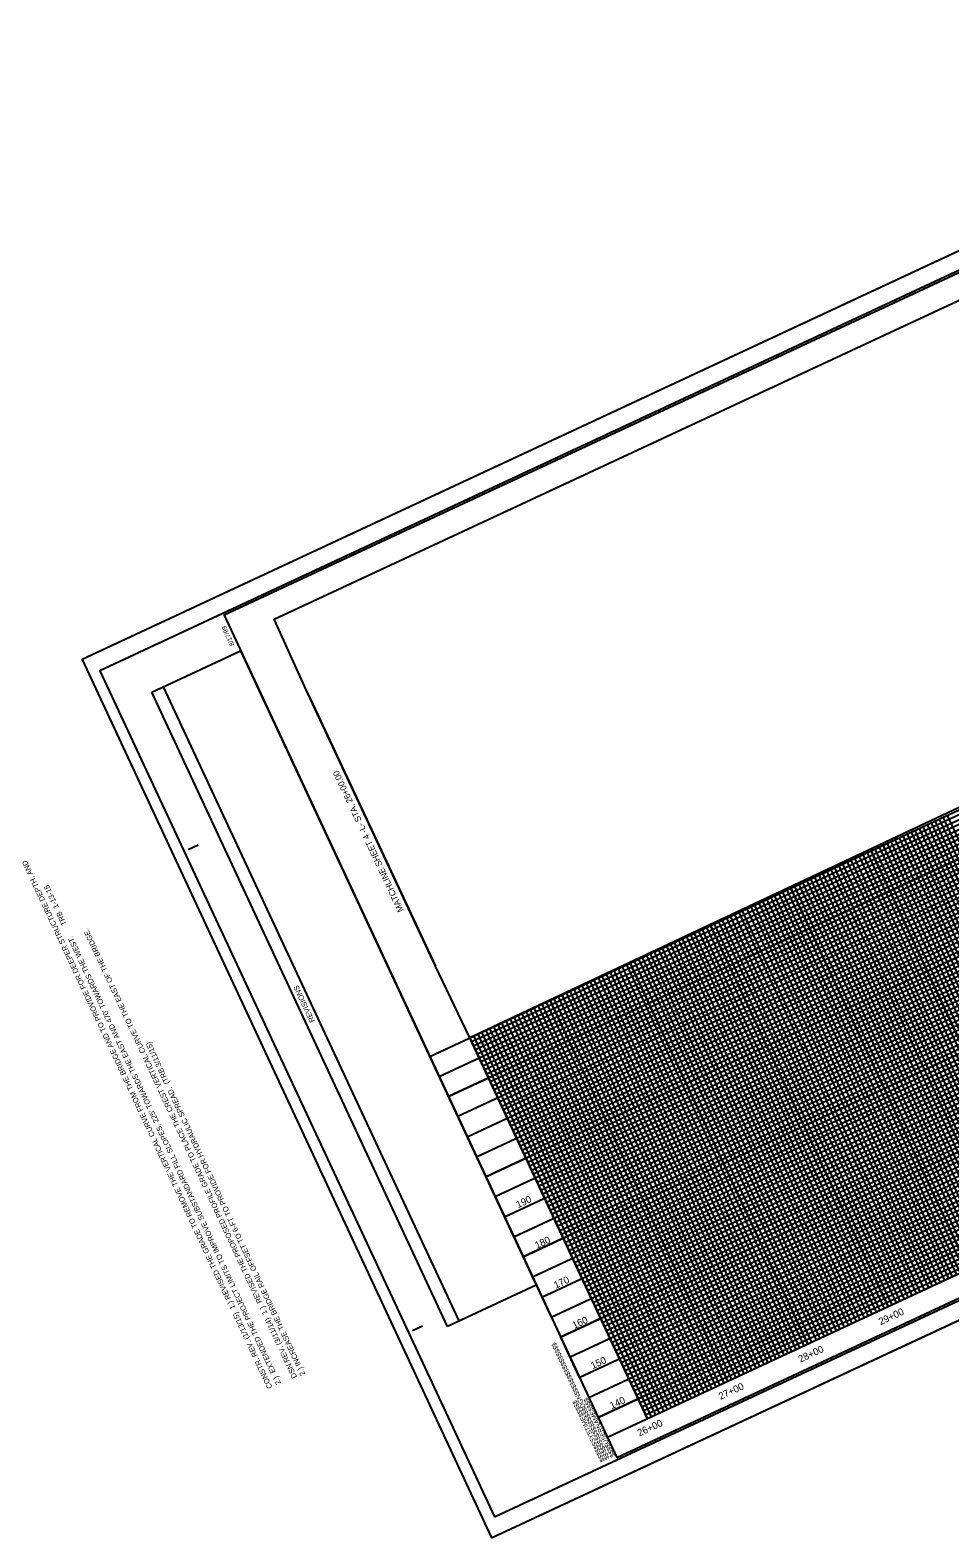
# Model space of a CAD drawing. Extents: x 2321825 to 2323872, y 921700 to 923436.
# Drawn here: x 2321825 to 2322864, y 921700 to 923403 of the extents above; entities that cross this region are included whole.
import ezdxf

# ---------------------------------------------------------------- set-up
doc = ezdxf.new("R2010")
doc.units = 0
for name, color, linetype in [('Default', 7, 'Continuous'), ('Matchline', 7, 'Continuous'), ('Matchline Text', 7, 'Continuous'), ('Sheet Block Revision CELL', 7, 'Continuous'), ('Sheet Block System Information CELL', 7, 'Continuous'), ('Sheet Cutting Line CELL', 7, 'Continuous'), ('Sheet DOT Grid CELL', 7, 'Continuous'), ('Sheet Layout Plan Border', 7, 'Continuous'), ('Sheet Layout Profile Border Port 2', 7, 'Continuous'), ('Sheet Plan And Profile CELL', 7, 'Continuous'), ('Sheet Plot Border Inside CELL', 7, 'Continuous'), ('Sheet Plot Border Outside CELL', 7, 'Continuous'), ('Sheet Profile Grid Major CELL', 7, 'Continuous'), ('Sheet Profile Grid Middle CELL', 7, 'Continuous'), ('Sheet Profile Grid Minor CELL', 7, 'Continuous')]:
    doc.layers.add(name, color=color, linetype=linetype)

# ---------------------------------------------------------------- blocks, each defined once
blk = doc.blocks.new('SYSTEM BLOCK')
at = {"layer": 'Sheet Block System Information CELL'}
blk.add_line((0, 0), (0, 0), dxfattribs=at)
for s, p in [('$$$$$$$$$$$$$$$$DGN$$$$$$$$$$$$$$$$', (-0.153, 0.04725)), ('$$$$$$SYSTIME$$$$$', (-0.274, 0.04725)), ('$$$$USERNAME$$$$', (-0.0215, 0.0475))]:
    blk.add_text(s, height=0.105, rotation=90, dxfattribs=at).set_placement(p)

msp = doc.modelspace()

# ---------------------------------------------------------------- linework, layer by layer
at = {"layer": 'Matchline'}
msp.add_line((2322138.6, 922653.9), (2322282.6, 922345.7), dxfattribs=at)
at = {"layer": 'Sheet Block Revision CELL'}
for p, q in [((2321962.4, 922655.1), (2322062.6, 922701.9)), ((2322062.6, 922701.9), (2322396.6, 921985.2)), ((2322296.4, 921938.5), (2321962.4, 922655.1)), ((2322309.6, 921944.7), (2321975.6, 922661.3)), ((2322396.6, 921985.2), (2322296.4, 921938.5))]:
    msp.add_line(p, q, dxfattribs=at)
at = {"layer": 'Sheet Cutting Line CELL'}
for p, q in [((2323409.3, 923403.3), (2321883.5, 922692.1)), ((2321883.5, 922692.1), (2322346.1, 921699.6)), ((2322346.1, 921699.6), (2323872, 922410.9))]:
    msp.add_line(p, q, dxfattribs=at)
at = {"layer": 'Sheet DOT Grid CELL'}
for p, q in [((2322276.2, 922243.5), (2323635.8, 922877.3)), ((2322297.4, 922198.2), (2323656.9, 922831.9)), ((2322318.5, 922152.9), (2323678, 922786.6)), ((2322339.6, 922107.6), (2323699.2, 922741.3)), ((2322360.7, 922062.3), (2323720.3, 922696)), ((2322381.9, 922017), (2323741.4, 922650.7)), ((2322403, 921971.6), (2323762.5, 922605.4)), ((2322424.1, 921926.3), (2323783.7, 922560)), ((2322445.2, 921881), (2323804.8, 922514.7)), ((2322820.1, 922497), (2323020.7, 922066.5)), ((2322466.4, 921835.7), (2323825.9, 922469.4)), ((2322774.7, 922475.9), (2322975.4, 922045.4)), ((2322729.4, 922454.8), (2322930.1, 922024.3)), ((2322684.1, 922433.7), (2322884.8, 922003.1)), ((2322638.8, 922412.5), (2322839.5, 921982)), ((2322593.5, 922391.4), (2322794.2, 921960.9)), ((2322548.2, 922370.3), (2322748.8, 921939.8)), ((2322502.8, 922349.2), (2322703.5, 921918.6)), ((2322457.5, 922328), (2322658.2, 921897.5)), ((2322412.2, 922306.9), (2322612.9, 921876.4)), ((2322366.9, 922285.8), (2322567.6, 921855.3)), ((2322321.6, 922264.7), (2322522.2, 921834.1))]:
    msp.add_line(p, q, dxfattribs=at)
at = {"layer": 'Sheet Layout Plan Border'}
msp.add_lwpolyline([(2323496.8, 922818), (2322321.6, 922264.7), (2322282.6, 922345.7), (2322138.6, 922653.9), (2322100.4, 922737.9), (2323278.1, 923286)], close=True, dxfattribs=at)
at = {"layer": 'Sheet Layout Profile Border Port 2'}
msp.add_lwpolyline([(2322321.6, 922264.7), (2323590.5, 922856.1), (2323791.2, 922425.6), (2322522.2, 921834.1)], close=True, dxfattribs=at)
at = {"layer": 'Sheet Plan And Profile CELL'}
for p, q in [((2322003.3, 922477.6), (2322014.6, 922482.9)), ((2323836.5, 922446.7), (2322476.9, 921813)), ((2322256.8, 921933.8), (2322268.1, 921939.1)), ((2322487.5, 921790.4), (2322487.5, 921790.4)), ((2322487.5, 921790.4), (2322487.5, 921790.4)), ((2322487.5, 921790.4), (2322487.5, 921790.4)), ((2322487.5, 921790.4), (2322487.5, 921790.4)), ((2322487.5, 921790.4), (2322487.5, 921790.4))]:
    msp.add_line(p, q, dxfattribs=at)
msp.add_lwpolyline([(2323403.4, 923375.8), (2322043.9, 922742.1), (2322487.5, 921790.4), (2323847, 922424.1)], close=True, dxfattribs=at)
at = {"layer": 'Sheet Plot Border Inside CELL'}
msp.add_lwpolyline([(2322349.4, 921723.2), (2323859.4, 922427.1), (2323413.7, 923383.3), (2321903.7, 922679.5)], close=True, dxfattribs=at)
at = {"layer": 'Sheet Plot Border Outside CELL'}
msp.add_lwpolyline([(2322346.1, 921699.6), (2323872, 922410.9), (2323409.3, 923403.3), (2321883.5, 922692.1)], close=True, dxfattribs=at)
at = {"layer": 'Sheet Profile Grid Major CELL'}
for points in [[(2322276.2, 922243.5), (2323635.8, 922877.3)], [(2323656.9, 922831.9), (2322297.4, 922198.2), (2322318.5, 922152.9), (2323678, 922786.6)], [(2323699.2, 922741.3), (2322339.6, 922107.6), (2322360.7, 922062.3), (2323720.3, 922696)], [(2323741.4, 922650.7), (2322381.9, 922017), (2322403, 921971.6), (2323762.5, 922605.4)], [(2323783.7, 922560), (2322424.1, 921926.3), (2322445.2, 921881), (2323804.8, 922514.7)], [(2322975.4, 922045.4), (2322774.7, 922475.9), (2322820.1, 922497), (2323020.7, 922066.5)], [(2323825.9, 922469.4), (2322466.4, 921835.7)], [(2322884.8, 922003.1), (2322684.1, 922433.7), (2322729.4, 922454.8), (2322930.1, 922024.3)], [(2322794.2, 921960.9), (2322593.5, 922391.4), (2322638.8, 922412.5), (2322839.5, 921982)], [(2322703.5, 921918.6), (2322502.8, 922349.2), (2322548.2, 922370.3), (2322748.8, 921939.8)], [(2322612.9, 921876.4), (2322412.2, 922306.9), (2322457.5, 922328), (2322658.2, 921897.5)], [(2322522.2, 921834.1), (2322321.6, 922264.7), (2322366.9, 922285.8), (2322567.6, 921855.3)], [(2322276.2, 922243.5), (2322476.9, 921813)]]:
    msp.add_lwpolyline(points, dxfattribs=at)
at = {"layer": 'Sheet Profile Grid Middle CELL'}
for p, q in [((2322286.8, 922220.9), (2323646.4, 922854.6)), ((2323667.5, 922809.3), (2322307.9, 922175.6)), ((2322329.1, 922130.3), (2323688.6, 922764)), ((2323709.7, 922718.7), (2322350.2, 922084.9)), ((2322371.3, 922039.6), (2323730.9, 922673.3)), ((2323752, 922628), (2322392.4, 921994.3)), ((2322413.5, 921949), (2323773.1, 922582.7)), ((2323794.2, 922537.4), (2322434.7, 921903.7)), ((2322455.8, 921858.3), (2323815.4, 922492.1)), ((2322307.9, 922175.6), (2322329.1, 922130.3)), ((2322350.2, 922084.9), (2322371.3, 922039.6)), ((2322392.4, 921994.3), (2322413.5, 921949)), ((2322434.7, 921903.7), (2322455.8, 921858.3))]:
    msp.add_line(p, q, dxfattribs=at)
for points in [[(2322998.1, 922055.9), (2322797.4, 922486.5), (2322842.7, 922507.6), (2323043.4, 922077.1)], [(2322907.4, 922013.7), (2322706.8, 922444.2), (2322752.1, 922465.3), (2322952.8, 922034.8)], [(2322816.8, 921971.5), (2322616.1, 922402), (2322661.5, 922423.1), (2322862.1, 921992.6)], [(2322726.2, 921929.2), (2322525.5, 922359.7), (2322570.8, 922380.9), (2322771.5, 921950.3)], [(2322635.5, 921887), (2322434.9, 922317.5), (2322480.2, 922338.6), (2322680.9, 921908.1)], [(2322544.9, 921844.7), (2322344.2, 922275.2), (2322389.5, 922296.4), (2322590.2, 921865.8)]]:
    msp.add_lwpolyline(points, dxfattribs=at)
at = {"layer": 'Sheet Profile Grid Minor CELL'}
for points in [[(2323592.6, 922851.6), (2322323.7, 922260.1)], [(2323596.8, 922842.5), (2322327.9, 922251.1), (2322325.8, 922255.6), (2323594.7, 922847.1)], [(2323603.2, 922829), (2322334.2, 922237.5), (2322332.1, 922242), (2322330, 922246.5), (2323598.9, 922838)], [(2323607.4, 922819.9), (2322338.5, 922228.4), (2322336.3, 922232.9), (2323605.3, 922824.4)], [(2323613.7, 922806.3), (2322344.8, 922214.8), (2322342.7, 922219.4), (2322340.6, 922223.9), (2323609.5, 922815.4)], [(2323617.9, 922797.2), (2322349, 922205.8), (2322346.9, 922210.3), (2323615.8, 922801.8)], [(2323624.3, 922783.6), (2322355.4, 922192.2), (2322353.2, 922196.7), (2322351.1, 922201.2), (2323620.1, 922792.7)], [(2323628.5, 922774.6), (2322359.6, 922183.1), (2322357.5, 922187.6), (2323626.4, 922779.1)], [(2322365.9, 922169.5), (2322363.8, 922174), (2322361.7, 922178.6), (2323630.6, 922770)], [(2323637, 922756.4), (2322368, 922165), (2322365.9, 922169.5), (2323634.8, 922761)], [(2323641.2, 922747.4), (2322372.3, 922155.9), (2322370.1, 922160.4), (2323639.1, 922751.9)], [(2323647.5, 922733.8), (2322378.6, 922142.3), (2322376.5, 922146.8), (2323645.4, 922738.3)], [(2323651.7, 922724.7), (2322382.8, 922133.2), (2322380.7, 922137.8), (2323649.6, 922729.3)], [(2323658.1, 922711.1), (2322389.2, 922119.7), (2322387, 922124.2), (2323656, 922715.7)], [(2323662.3, 922702.1), (2322393.4, 922110.6), (2322391.3, 922115.1), (2323660.2, 922706.6)], [(2323668.6, 922688.5), (2322399.7, 922097), (2322397.6, 922101.5), (2323666.5, 922693)], [(2323672.9, 922679.4), (2322403.9, 922087.9), (2322401.8, 922092.5), (2323670.8, 922683.9)], [(2323679.2, 922665.8), (2322410.3, 922074.3), (2322408.2, 922078.9), (2323677.1, 922670.3)], [(2323683.4, 922656.7), (2322414.5, 922065.3), (2322412.4, 922069.8), (2323681.3, 922661.3)], [(2323689.8, 922643.1), (2322420.8, 922051.7), (2322418.7, 922056.2), (2323687.7, 922647.7)], [(2323694, 922634.1), (2322425.1, 922042.6), (2322423, 922047.1), (2323691.9, 922638.6)], [(2323700.3, 922620.5), (2322431.4, 922029), (2322429.3, 922033.5), (2323698.2, 922625)], [(2323704.6, 922611.4), (2322435.6, 922020), (2322433.5, 922024.5), (2323702.4, 922616)], [(2323710.9, 922597.8), (2322442, 922006.4), (2322439.9, 922010.9), (2323708.8, 922602.4)], [(2323715.1, 922588.8), (2322446.2, 921997.3), (2322444.1, 922001.8), (2323713, 922593.3)], [(2323721.5, 922575.2), (2322452.5, 921983.7), (2322450.4, 921988.2), (2323719.3, 922579.7)], [(2323725.7, 922566.1), (2322456.8, 921974.6), (2322454.6, 921979.2), (2323723.6, 922570.6)], [(2323732, 922552.5), (2322463.1, 921961), (2322461, 921965.6), (2323729.9, 922557)], [(2323736.2, 922543.4), (2322467.3, 921952), (2322465.2, 921956.5), (2323734.1, 922548)], [(2323742.6, 922529.8), (2322473.7, 921938.4), (2322471.5, 921942.9), (2323740.5, 922534.4)], [(2323746.8, 922520.8), (2322477.9, 921929.3), (2322475.8, 921933.8), (2323744.7, 922525.3)], [(2323057, 922083.4), (2322856.3, 922513.9), (2322860.9, 922516), (2323061.5, 922085.5)], [(2323753.1, 922507.2), (2322484.2, 921915.7), (2322482.1, 921920.2), (2323751, 922511.7)], [(2323757.4, 922498.1), (2322488.4, 921906.7), (2322486.3, 921911.2), (2323755.2, 922502.7)], [(2323025.3, 922068.6), (2322824.6, 922499.1), (2322829.1, 922501.3), (2323029.8, 922070.7)], [(2323034.3, 922072.8), (2322833.7, 922503.4), (2322838.2, 922505.5), (2323038.9, 922075)], [(2323047.9, 922079.2), (2322847.3, 922509.7), (2322851.8, 922511.8), (2323052.5, 922081.3)], [(2322494.8, 921893.1), (2322492.7, 921897.6), (2323761.6, 922489.1)], [(2322520.1, 921838.7), (2323789, 922430.1), (2323786.9, 922434.7), (2322518, 921843.2), (2322515.9, 921847.7), (2323784.8, 922439.2), (2323782.7, 922443.7), (2322513.8, 921852.3), (2322511.7, 921856.8), (2322509.6, 921861.3), (2323778.5, 922452.8), (2323776.4, 922457.3), (2322507.5, 921865.9), (2322505.3, 921870.4), (2323774.3, 922461.9), (2323772.1, 922466.4), (2322503.2, 921874.9), (2322501.1, 921879.5), (2322499, 921884), (2323767.9, 922475.5), (2323765.8, 922480), (2322496.9, 921888.5), (2322494.8, 921893.1), (2323763.7, 922484.5)], [(2322989, 922051.7), (2322788.3, 922482.2), (2322792.9, 922484.4), (2322993.6, 922053.8)], [(2323002.6, 922058.1), (2322801.9, 922488.6), (2322806.5, 922490.7), (2323007.1, 922060.2)], [(2323011.7, 922062.3), (2322811, 922492.8), (2322815.5, 922494.9), (2323016.2, 922064.4)], [(2322957.3, 922036.9), (2322756.6, 922467.5), (2322761.2, 922469.6), (2322961.8, 922039)], [(2322966.4, 922041.2), (2322765.7, 922471.7), (2322770.2, 922473.8), (2322970.9, 922043.3)], [(2322980, 922047.5), (2322779.3, 922478), (2322783.8, 922480.1), (2322984.5, 922049.6)], [(2322912, 922015.8), (2322711.3, 922446.3), (2322715.8, 922448.5), (2322916.5, 922017.9)], [(2322921, 922020), (2322720.4, 922450.6), (2322724.9, 922452.7), (2322925.6, 922022.1)], [(2322934.6, 922026.4), (2322734, 922456.9), (2322738.5, 922459), (2322939.2, 922028.5)], [(2322943.7, 922030.6), (2322743, 922461.1), (2322747.6, 922463.2), (2322948.2, 922032.7)], [(2322875.7, 921998.9), (2322675, 922429.4), (2322679.6, 922431.6), (2322880.3, 922001)], [(2322889.3, 922005.2), (2322688.6, 922435.8), (2322693.2, 922437.9), (2322893.9, 922007.4)], [(2322898.4, 922009.5), (2322697.7, 922440), (2322702.2, 922442.1), (2322902.9, 922011.6)], [(2322844, 921984.1), (2322643.3, 922414.7), (2322647.9, 922416.8), (2322848.5, 921986.2)], [(2322853.1, 921988.3), (2322652.4, 922418.9), (2322656.9, 922421), (2322857.6, 921990.5)], [(2322866.7, 921994.7), (2322666, 922425.2), (2322670.5, 922427.3), (2322871.2, 921996.8)], [(2322807.7, 921967.2), (2322607.1, 922397.8), (2322611.6, 922399.9), (2322812.3, 921969.3)], [(2322821.3, 921973.6), (2322620.7, 922404.1), (2322625.2, 922406.2), (2322825.9, 921975.7)], [(2322830.4, 921977.8), (2322629.7, 922408.3), (2322634.3, 922410.4), (2322834.9, 921979.9)], [(2322776, 921952.4), (2322575.3, 922383), (2322579.9, 922385.1), (2322780.6, 921954.6)], [(2322785.1, 921956.7), (2322584.4, 922387.2), (2322588.9, 922389.3), (2322789.6, 921958.8)], [(2322798.7, 921963), (2322598, 922393.5), (2322602.5, 922395.6), (2322803.2, 921965.1)], [(2322730.7, 921931.3), (2322530, 922361.8), (2322534.6, 922364), (2322735.2, 921933.4)], [(2322739.8, 921935.5), (2322539.1, 922366.1), (2322543.6, 922368.2), (2322744.3, 921937.7)], [(2322753.4, 921941.9), (2322552.7, 922372.4), (2322557.2, 922374.5), (2322757.9, 921944)], [(2322762.4, 921946.1), (2322561.7, 922376.6), (2322566.3, 922378.7), (2322767, 921948.2)], [(2322694.4, 921914.4), (2322493.8, 922344.9), (2322498.3, 922347.1), (2322699, 921916.5)], [(2322708, 921920.8), (2322507.4, 922351.3), (2322511.9, 922353.4), (2322712.6, 921922.9)], [(2322717.1, 921925), (2322516.4, 922355.5), (2322521, 922357.6), (2322721.6, 921927.1)], [(2322662.7, 921899.6), (2322462, 922330.2), (2322466.6, 922332.3), (2322667.3, 921901.7)], [(2322671.8, 921903.9), (2322471.1, 922334.4), (2322475.6, 922336.5), (2322676.3, 921906)], [(2322685.4, 921910.2), (2322484.7, 922340.7), (2322489.2, 922342.8), (2322689.9, 921912.3)], [(2322617.4, 921878.5), (2322416.7, 922309), (2322421.3, 922311.1), (2322621.9, 921880.6)], [(2322626.5, 921882.7), (2322425.8, 922313.3), (2322430.3, 922315.4), (2322631, 921884.8)], [(2322640.1, 921889.1), (2322439.4, 922319.6), (2322443.9, 922321.7), (2322644.6, 921891.2)], [(2322649.1, 921893.3), (2322448.5, 922323.8), (2322453, 922325.9), (2322653.7, 921895.4)], [(2322581.2, 921861.6), (2322380.5, 922292.1), (2322385, 922294.2), (2322585.7, 921863.7)], [(2322594.7, 921867.9), (2322394.1, 922298.5), (2322398.6, 922300.6), (2322599.3, 921870.1)], [(2322603.8, 921872.2), (2322403.1, 922302.7), (2322407.7, 922304.8), (2322608.3, 921874.3)], [(2322549.4, 921846.8), (2322348.8, 922277.3), (2322353.3, 922279.5), (2322554, 921848.9)], [(2322558.5, 921851), (2322357.8, 922281.6), (2322362.3, 922283.7), (2322563, 921853.2)], [(2322572.1, 921857.4), (2322371.4, 922287.9), (2322375.9, 922290), (2322576.6, 921859.5)], [(2322526.8, 921836.3), (2322326.1, 922266.8), (2322330.6, 922268.9), (2322531.3, 921838.4)], [(2322535.8, 921840.5), (2322335.2, 922271), (2322339.7, 922273.1), (2322540.4, 921842.6)]]:
    msp.add_lwpolyline(points, dxfattribs=at)

# ---------------------------------------------------------------- block references
at = {"layer": 'Sheet Block System Information CELL', "xscale": 49.99999999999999, "yscale": 50, "rotation": 24.991298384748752}
msp.add_blockref('SYSTEM BLOCK', (2322487.5, 921790.4), dxfattribs=at)

# ---------------------------------------------------------------- texts
at = {"layer": 'Default'}
for s, p in [('190', (2322375.9, 922072)), ('180', (2322397.2, 922026.1)), ('170', (2322418.6, 921981)), ('29+00', (2322785.6, 921939.8)), ('160', (2322439.5, 921935.6)), ('150', (2322460.4, 921890.1)), ('28+00', (2322694.9, 921897.5)), ('27+00', (2322604.8, 921855.4)), ('140', (2322481.8, 921844.9)), ('26+00', (2322513, 921814))]:
    msp.add_text(s, height=8, rotation=24.9913, dxfattribs=at).set_placement(p)
at = {"layer": 'Matchline Text'}
msp.add_text('MATCHLINE SHEET 4 -L- STA. 26+00.00', height=7, rotation=114.9913, dxfattribs=at).set_placement((2322246.9, 922408.7))
at = {"layer": 'Sheet Block Revision CELL'}
for s, p in [('CONSTR. REV. (1/13/15)  1.) REVISED THE GRADE TO REMOVE THE VERTICAL CURVE FROM THE BRIDGE AND TO PROVIDE FOR DEEPER STRUCTURE DEPTH, AND          ', (2322098.6, 921869.7)), ("2.)  EXTENDED THE PROJECT LIMITS TO IMPROVE SUBSTANDARD FILL SLOPES, 225' TOWARDS THE EAST AND 470' TOWARDS THE WEST.      TRB  1-13-15            ", (2322108.3, 921874.2)), ('DSN REV. (3/11/14)  1.)  REVISED THE PROPOSED PROFILE GRADE TO PLACE THE CREST VERTICAL CURVE TO THE EAST OF THE BRIDGE.        ', (2322126.5, 921881.5)), ('REVISIONS', (2322146.5, 922283.7)), ('2.) INCREASE THE BRIDGE RAIL OFFSET TO 6-FT TO PROVIDE FOR HYDRAULIC SPREAD.  (TRB 3/11/15)                                     ', (2322135.9, 921884.5))]:
    msp.add_text(s, height=6, rotation=114.9913, dxfattribs=at).set_placement(p)
at = {"layer": 'Sheet Plan And Profile CELL'}
msp.add_text('8/17/99', height=5.25, rotation=114.9913, dxfattribs=at).set_placement((2322055.8, 922708.8))

doc.saveas('drawing.dxf')
